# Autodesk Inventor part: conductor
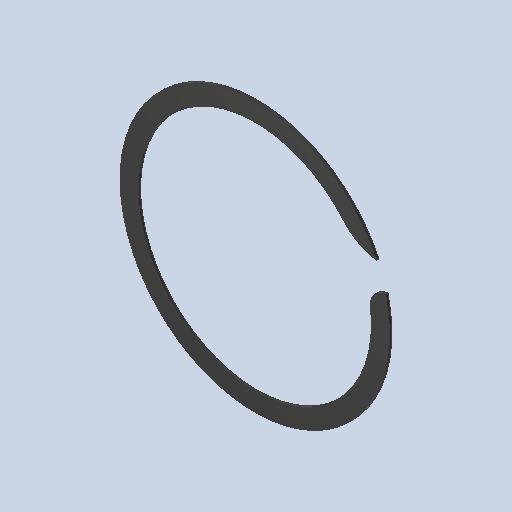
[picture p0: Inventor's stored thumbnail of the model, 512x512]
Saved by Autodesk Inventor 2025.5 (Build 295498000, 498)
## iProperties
Created: 2018-09
Part Number: conductor
Material: Generic
Document SubType Name: Modeling
Designer: Ev
Density: 1 g/cm^3
Appearance: Default
Author: Ev
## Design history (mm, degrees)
derived "fsr_DF9-40.ipt"
feature "conductor::fsr_DF9-40.ipt" dims "d0" = 10
tag "TaggingFeature1"
body "Solid1"
